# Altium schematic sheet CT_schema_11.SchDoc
size 146 x 119 mm
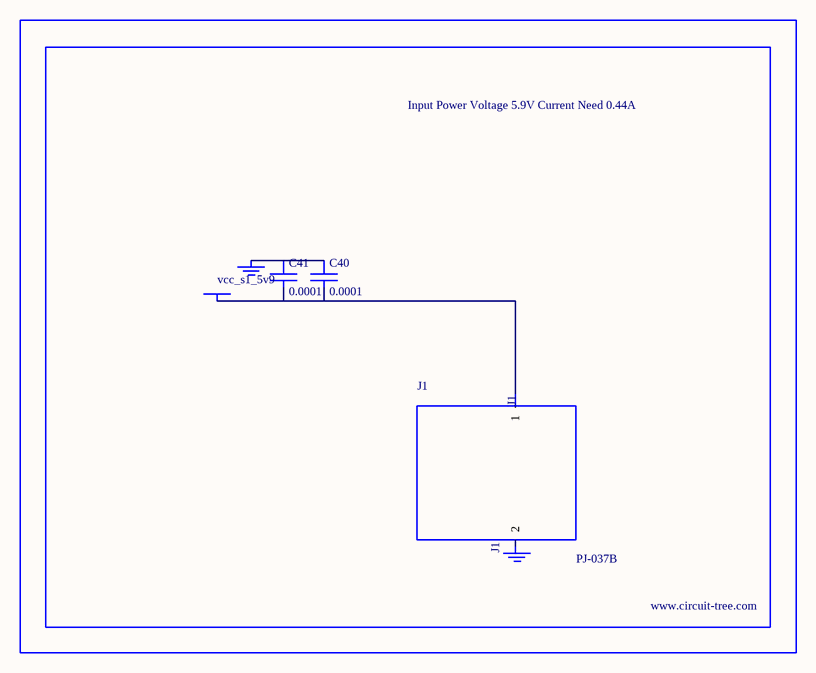
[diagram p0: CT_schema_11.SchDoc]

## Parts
BORDER10  (no value)
C40  0.0001  [EXV-9H]
C41  0.0001  [EXV-9H]
GND_INSTANCE_10_0  (no value)
GND_INSTANCE_10_1  (no value)
J1  PJ-037B  [PJ-037B_PACKAGE]
POWER_INSTANCE_10_0  vcc_s1_5v9

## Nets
NetC40_1: C40.1 C41.1 GND_INSTANCE_10_0.0(GND)
NetC40_2: C40.2 C41.2 J1.1 POWER_INSTANCE_10_0.0(PWR)

Not connected (* = marked no-connect by the designer): GND_INSTANCE_10_1 0(GND); J1 2

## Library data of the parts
BORDER10 = BORDER_PAGE10
C40 C41 = EDK107M035A9HAA
GND_INSTANCE_10_0 GND_INSTANCE_10_1 = GND
POWER_INSTANCE_10_0 = PWR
